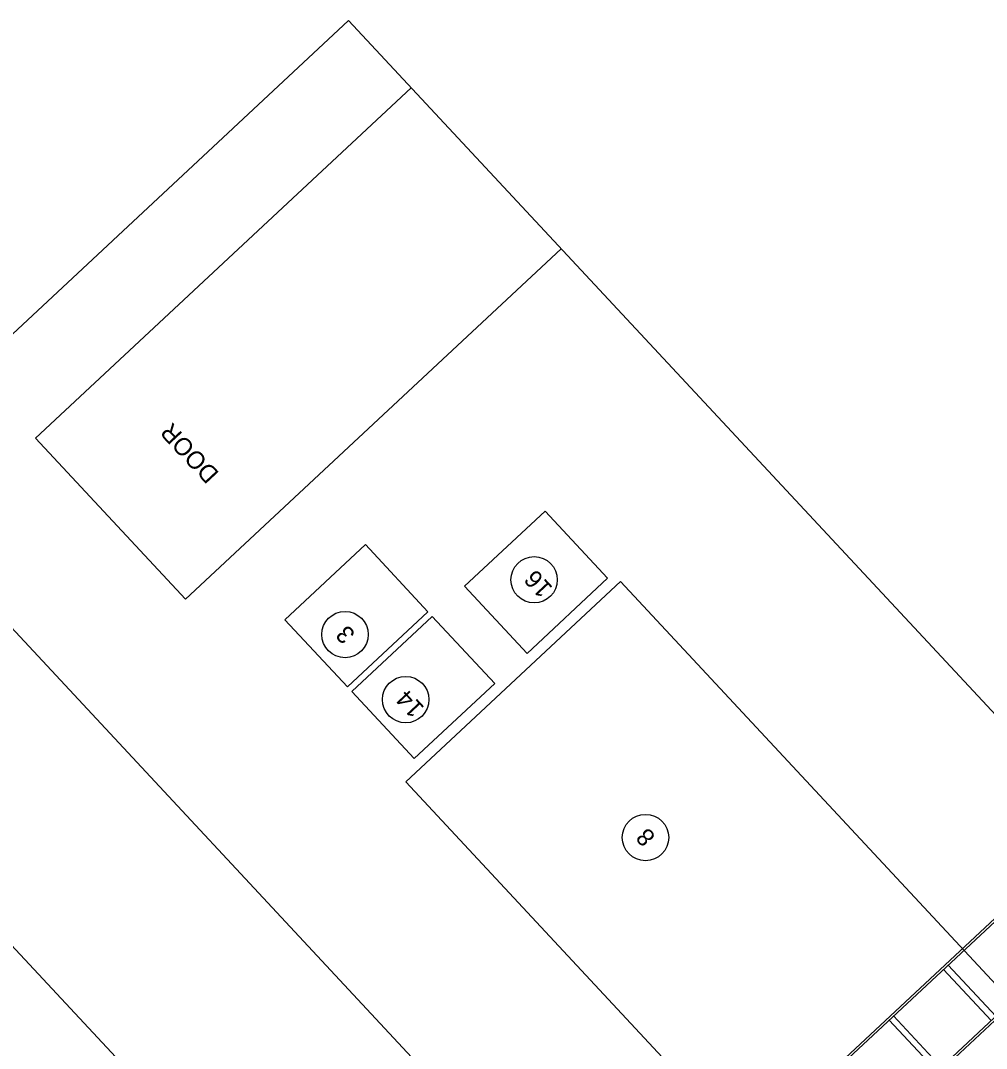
# Model space of a CAD drawing. Extents: x 1121979 to 1130574, y 1838676 to 1848573.
# Drawn here: x 1129644.21 to 1129657.38, y 1839365.55 to 1839379.56 of the extents above; entities that cross this region are included whole.
import ezdxf

# ---------------------------------------------------------------- set-up
doc = ezdxf.new("R2010")
doc.units = 0
for name, color, linetype in [('CLB-6', 7, 'Continuous'), ('IPDC BUILDING RELATED', 7, 'Continuous'), ('IPDC-EXIST ELECT EQUIP', 7, 'Continuous'), ('IPDC-PROP ELECT EQUIP', 7, 'Continuous'), ('Level 4', 7, 'Continuous')]:
    doc.layers.add(name, color=color, linetype=linetype)

# ---------------------------------------------------------------- blocks, each defined once
blk = doc.blocks.new('CLB_61')
at = {"layer": 'CLB-6'}
for p, q in [((0.095, 18.288), (0, 18.288)), ((0, 18.288), (0, 0)), ((0.095, 18.288), (0.095, 0)), ((3.048, 18.288), (2.953, 18.288)), ((2.953, 18.288), (2.953, 0)), ((3.048, 18.288), (3.048, 0)), ((0.095, 16.891), (2.953, 16.891)), ((0.095, 16.637), (2.953, 16.637)), ((0.098, 15.621), (0.098, 14.859)), ((0.095, 13.843), (2.953, 13.843)), ((0.095, 13.589), (2.953, 13.589)), ((0.095, 10.795), (2.953, 10.795)), ((0.095, 10.541), (2.953, 10.541)), ((0.095, 7.747), (2.953, 7.747)), ((0.095, 7.493), (2.953, 7.493)), ((0.095, 4.699), (2.953, 4.699)), ((0.095, 4.445), (2.953, 4.445)), ((0.098, 3.429), (0.098, 2.667)), ((2.95, 2.667), (2.95, 3.429)), ((0.095, 1.651), (2.953, 1.651)), ((0.095, 1.397), (2.953, 1.397)), ((0.095, 0), (0, 0)), ((3.048, 0), (2.953, 0))]:
    blk.add_line(p, q, dxfattribs=at)

msp = doc.modelspace()

# ---------------------------------------------------------------- linework, layer by layer
at = {"layer": 'IPDC BUILDING RELATED'}
for p, q in [((1129648.683, 1839379.557), (1129642.1, 1839373.419)), ((1129668.039, 1839358.794), (1129648.683, 1839379.557)), ((1129642.1, 1839373.419), (1129661.457, 1839352.656)), ((1129639.942, 1839371.407), (1129659.302, 1839350.647))]:
    msp.add_line(p, q, dxfattribs=at)
at = {"layer": 'IPDC-EXIST ELECT EQUIP'}
for p, q in [((1129649.535, 1839378.642), (1129644.415, 1839373.869)), ((1129651.581, 1839376.448), (1129646.461, 1839371.674)), ((1129644.415, 1839373.869), (1129646.461, 1839371.674)), ((1129647.815, 1839371.394), (1129648.912, 1839372.417)), ((1129648.912, 1839372.417), (1129649.764, 1839371.503)), ((1129649.463, 1839369.186), (1129652.389, 1839371.914)), ((1129652.389, 1839371.914), (1129659.107, 1839364.708)), ((1129648.667, 1839370.48), (1129649.764, 1839371.503)), ((1129647.815, 1839371.394), (1129648.667, 1839370.48)), ((1129656.182, 1839361.98), (1129649.463, 1839369.186))]:
    msp.add_line(p, q, dxfattribs=at)
at = {"layer": 'IPDC-PROP ELECT EQUIP'}
for p, q in [((1129650.265, 1839371.851), (1129651.362, 1839372.873)), ((1129651.362, 1839372.873), (1129652.215, 1839371.959)), ((1129651.117, 1839370.936), (1129652.215, 1839371.959)), ((1129650.265, 1839371.851), (1129651.117, 1839370.936)), ((1129648.727, 1839370.416), (1129649.824, 1839371.439)), ((1129649.824, 1839371.439), (1129650.676, 1839370.525)), ((1129649.579, 1839369.502), (1129650.676, 1839370.525)), ((1129648.727, 1839370.416), (1129649.579, 1839369.502))]:
    msp.add_line(p, q, dxfattribs=at)
at = {"layer": 'Level 4'}
for centre in [(1129651.213, 1839371.939), (1129648.635, 1839371.192), (1129649.462, 1839370.306), (1129652.731, 1839368.427)]:
    msp.add_circle(centre, 0.316, dxfattribs=at)

# ---------------------------------------------------------------- block references
at = {"layer": 'IPDC-EXIST ELECT EQUIP', "xscale": 0.3332999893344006, "yscale": -0.3332999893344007, "rotation": 132.99714502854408}
msp.add_blockref('CLB_61', (1129654.153, 1839362.823), dxfattribs=at)

# ---------------------------------------------------------------- texts
at = {"layer": 'IPDC-EXIST ELECT EQUIP'}
msp.add_text('DOOR', height=0.24, rotation=132.9971, dxfattribs=at).set_placement((1129646.93, 1839373.391))
at = {"layer": 'Level 4'}
for s, p in [('16', (1129651.477, 1839371.831)), ('3', (1129648.787, 1839371.205)), ('14', (1129649.727, 1839370.197)), ('8', (1129652.879, 1839368.445))]:
    msp.add_text(s, height=0.24, rotation=132.9971, dxfattribs=at).set_placement(p)

doc.saveas('drawing.dxf')
